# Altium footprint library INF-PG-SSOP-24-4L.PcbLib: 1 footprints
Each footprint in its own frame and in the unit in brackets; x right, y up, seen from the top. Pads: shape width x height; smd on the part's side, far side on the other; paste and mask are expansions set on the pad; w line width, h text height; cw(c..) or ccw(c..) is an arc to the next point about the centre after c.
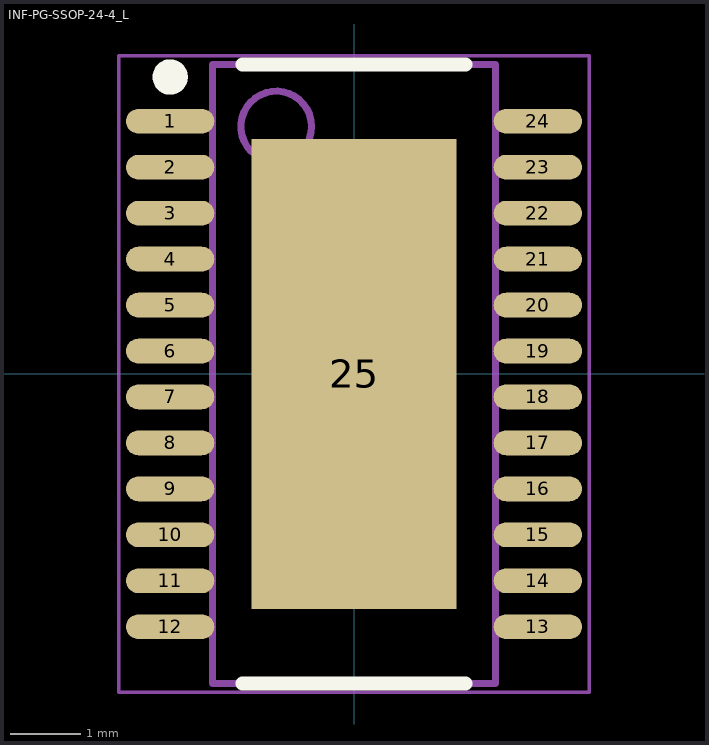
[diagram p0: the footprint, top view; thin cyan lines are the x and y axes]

## INF-PG-SSOP-24-4_L [mm] "SOP, 24-Leads, Body 8.65x3.9mm, Pitch 0.65mm, Thermal Pad 6.65x2.9mm, IPC High Density"
height 1.7
pads (25):
  oval 1.25x0.35 smd: 1(-2.6,3.575) 2(-2.6,2.925) 3(-2.6,2.275) 4(-2.6,1.625) 5(-2.6,0.975) 6(-2.6,0.325) 7(-2.6,-0.325) 8(-2.6,-0.975) 9(-2.6,-1.625) 10(-2.6,-2.275) 11(-2.6,-2.925) 12(-2.6,-3.575) 13(2.6,-3.575) 14(2.6,-2.925) 15(2.6,-2.275) 16(2.6,-1.625) 17(2.6,-0.975) 18(2.6,-0.325) 19(2.6,0.325) 20(2.6,0.975) 21(2.6,1.625) 22(2.6,2.275) 23(2.6,2.925) 24(2.6,3.575)
  rect 2.9x6.65 smd: 25(0,0)
Top Overlay:
  circle w0.25: c-2.6,4.2 r0.125
  lines w0.2: -1.575,-4.375 1.575,-4.375 ; -1.575,4.375 1.575,4.375
Mechanical 13:
  circle w0.1: c-1.1,3.5 r0.5
  lines w0.1: -2,-4.375 -2,4.375 2,4.375 2,-4.375 -2,-4.375
Mechanical 15:
  lines w0.05: -3.325,-4.5 -3.325,4.5 3.325,4.5 3.325,-4.5 -3.325,-4.5
  lines w0.1: -0.5,0 0.5,0 ; 0,-0.5 0,0.5
3D body: height 1.7, standoff 0, extent -2,-4.375 2,4.375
